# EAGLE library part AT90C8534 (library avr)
MICROCONTROLLER 8 Kbytes FLASH 512 bytes EEPROM 256 bytes SRAM 6-channel 10-bit A/D
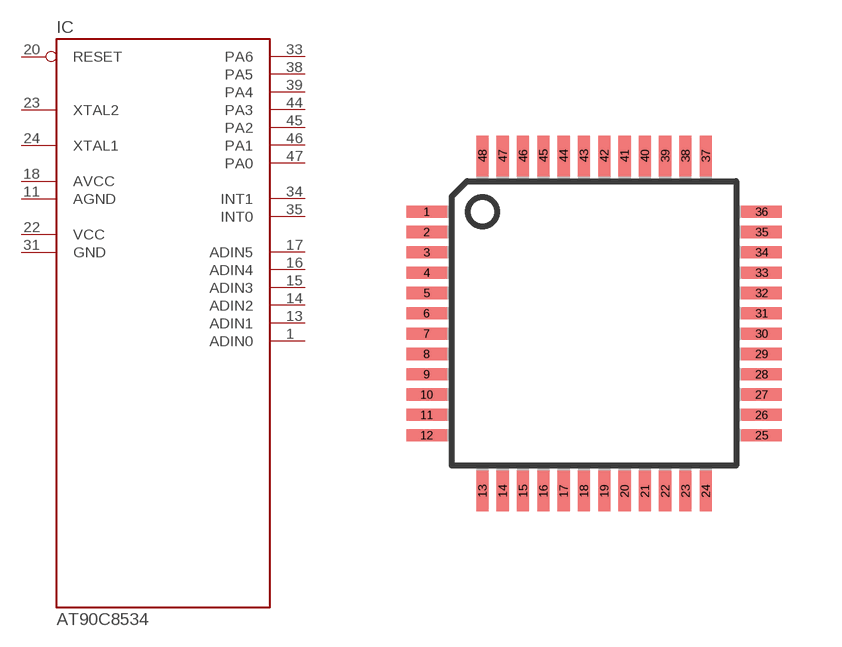
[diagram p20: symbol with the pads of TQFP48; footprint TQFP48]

Designator prefix IC

## AT90C8534A  [TQFP48]
1  ADIN0  in
2  NC1  nc
3  NC2  nc
4  NC3  nc
5  NC4  nc
6  NC5  nc
7  NC6  nc
8  NC7  nc
9  NC8  nc
10  NC9  nc
11  AGND  in
12  NC10  nc
13  ADIN1  in
14  ADIN2  in
15  ADIN3  in
16  ADIN4  in
17  ADIN5  in
18  AVCC  in
19  NC11  nc
20  RESET  in
21  NC12  nc
22  VCC  pwr
23  XTAL2
24  XTAL1
25  NC13  nc
26  NC14  nc
27  NC15  nc
28  NC16  nc
29  NC17  nc
30  NC18  nc
31  GND  pwr
32  NC19  nc
33  PA6
34  INT1  in
35  INT0  in
36  NC20  nc
37  NC21  nc
38  PA5
39  PA4
40  NC22  nc
41  NC23  nc
42  NC24  nc
43  NC25  nc
44  PA3
45  PA2
46  PA1
47  PA0
48  NC26  nc

## Footprint TQFP48 (pad centres in mm)
Thin Plasic Quad Flat Package
smd 1.016 x 0.305: 1 -4.191,2.794; 2 -4.191,2.286; 3 -4.191,1.778; 4 -4.191,1.27; 5 -4.191,0.762; 6 -4.191,0.254; 7 -4.191,-0.254; 8 -4.191,-0.762; 9 -4.191,-1.27; 10 -4.191,-1.778; 11 -4.191,-2.286; 12 -4.191,-2.794; 25 4.191,-2.794; 26 4.191,-2.286; 27 4.191,-1.778; 28 4.191,-1.27; 29 4.191,-0.762; 30 4.191,-0.254; 31 4.191,0.254; 32 4.191,0.762; 33 4.191,1.27; 34 4.191,1.778; 35 4.191,2.286; 36 4.191,2.794
smd 0.305 x 1.016: 13 -2.794,-4.191; 14 -2.286,-4.191; 15 -1.778,-4.191; 16 -1.27,-4.191; 17 -0.762,-4.191; 18 -0.254,-4.191; 19 0.254,-4.191; 20 0.762,-4.191; 21 1.27,-4.191; 22 1.778,-4.191; 23 2.286,-4.191; 24 2.794,-4.191; 37 2.794,4.191; 38 2.286,4.191; 39 1.778,4.191; 40 1.27,4.191; 41 0.762,4.191; 42 0.254,4.191; 43 -0.254,4.191; 44 -0.762,4.191; 45 -1.27,4.191; 46 -1.778,4.191; 47 -2.286,4.191; 48 -2.794,4.191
